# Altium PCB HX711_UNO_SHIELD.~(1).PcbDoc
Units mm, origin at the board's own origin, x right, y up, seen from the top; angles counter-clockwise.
Board outline 53.34 x 40.64 mm, 2 copper layers (Top Layer, Bottom Layer); 5 components, 8 nets, 35 pads, 0 vias.
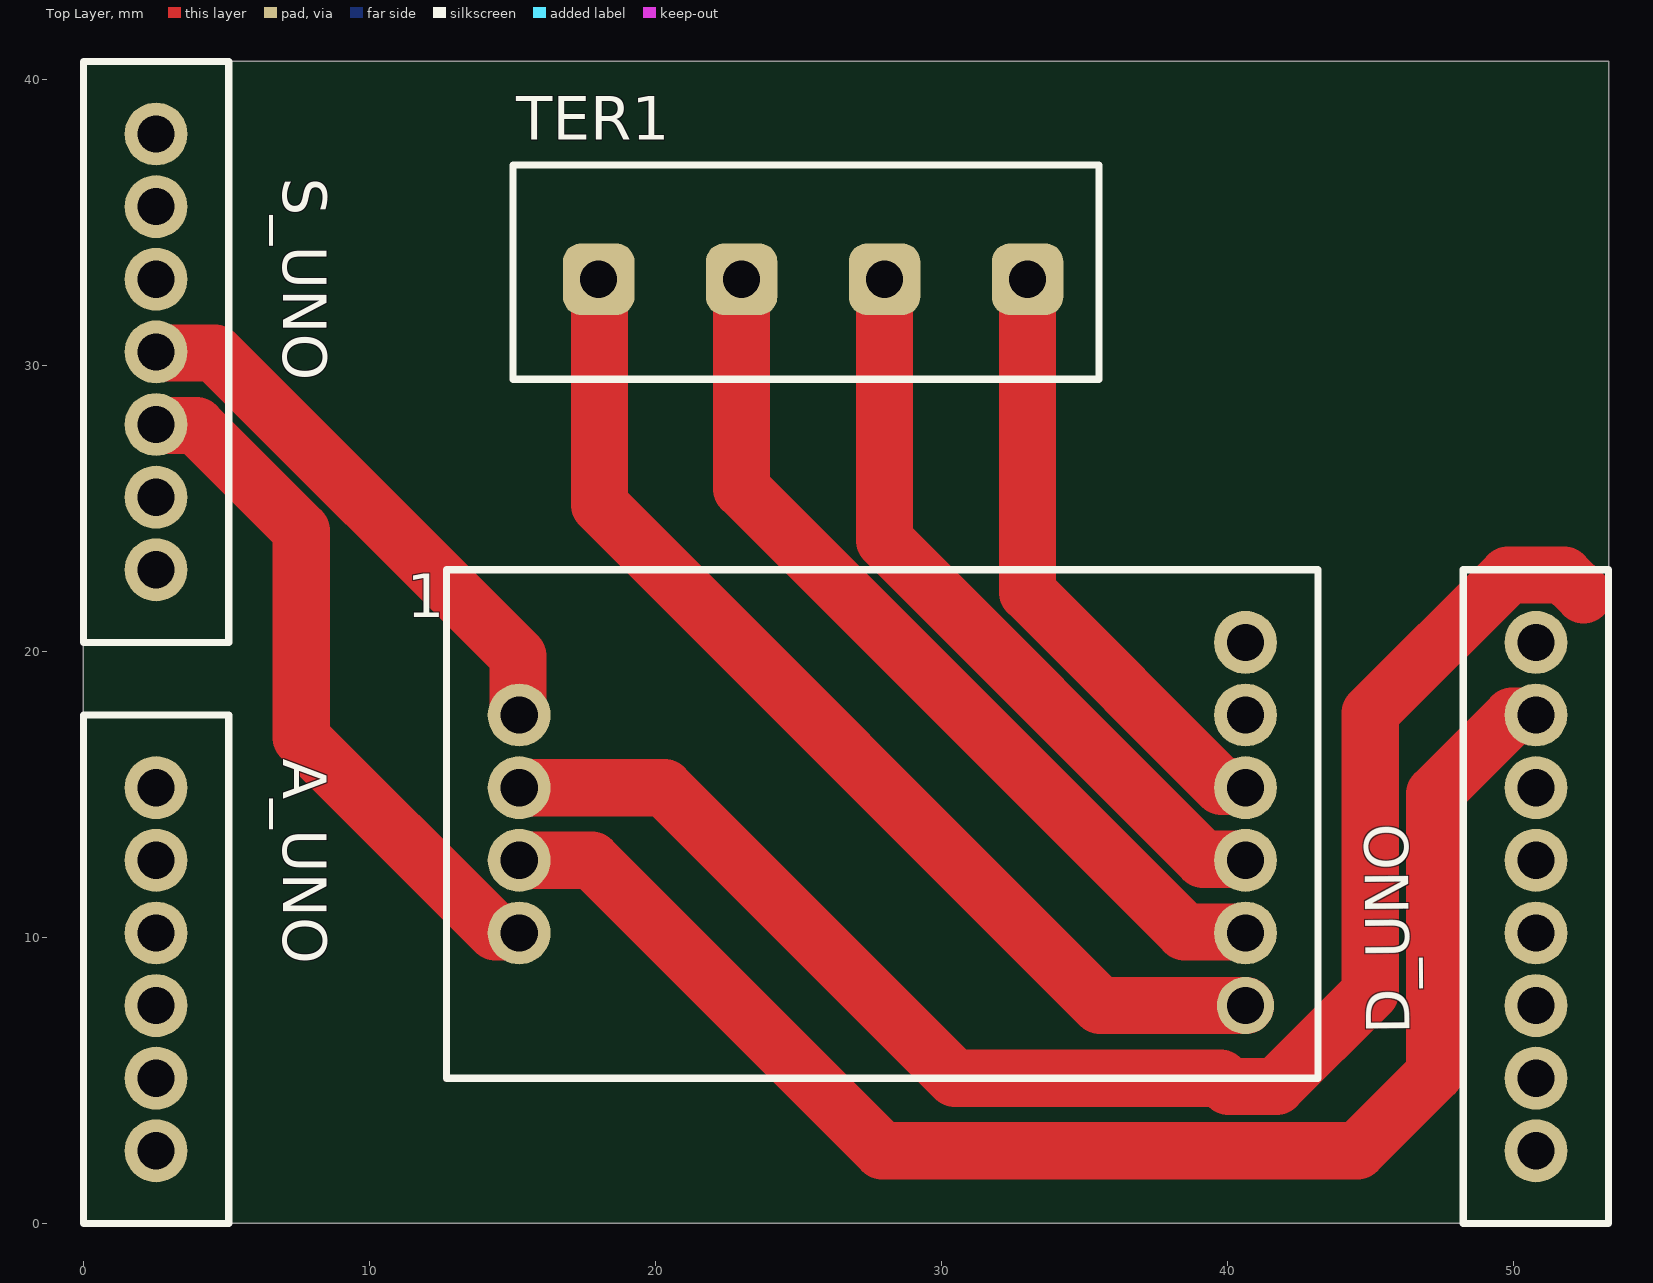
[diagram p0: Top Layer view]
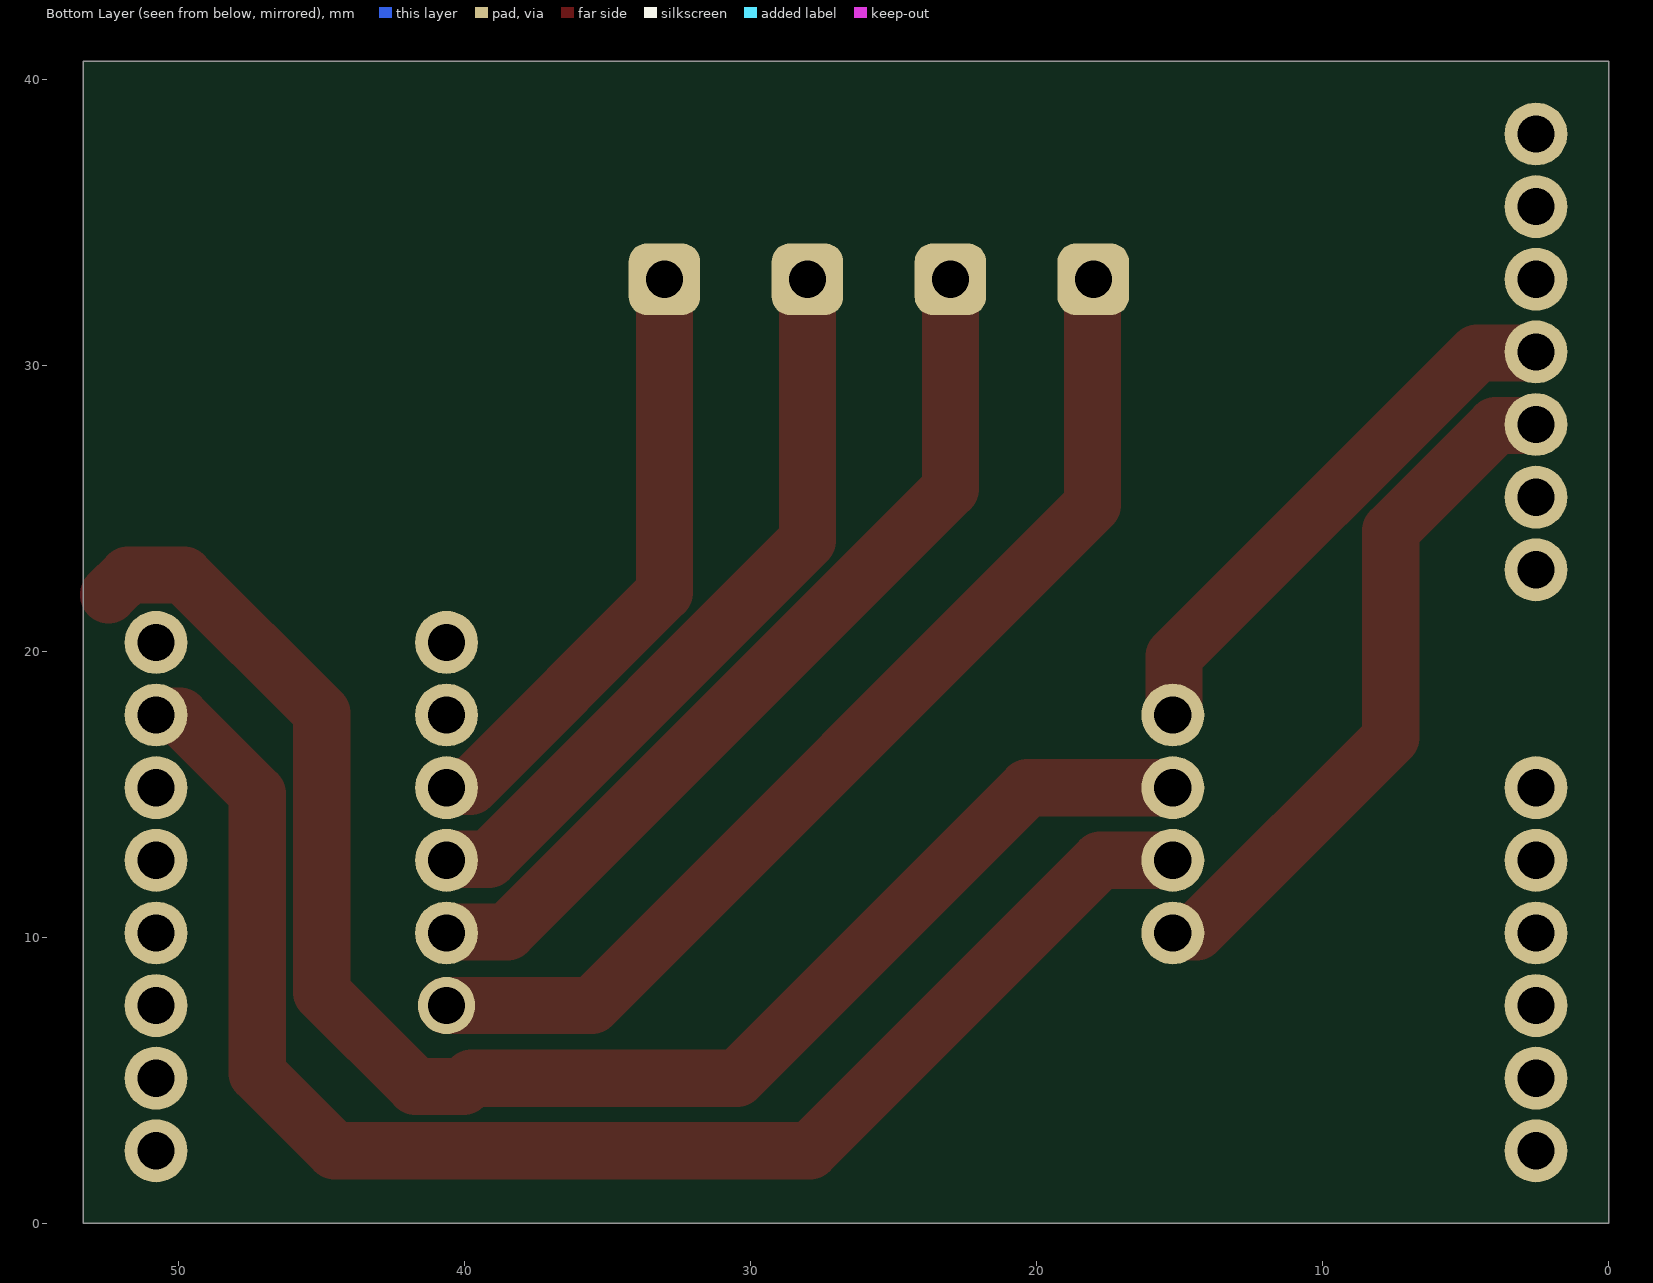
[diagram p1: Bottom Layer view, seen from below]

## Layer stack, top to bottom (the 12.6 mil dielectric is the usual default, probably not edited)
Top Solder: solder mask 0.0102, Solder Resist, Dk 3.5
Top Layer: signal copper 0.0356
Dielectric 1: dielectric 0.32, FR-4, Dk 4.8
Bottom Layer: signal copper 0.0356
Bottom Solder: solder mask 0.0102, Solder Resist, Dk 3.5

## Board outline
0,0 53.34,0 53.34,40.64 0,40.64

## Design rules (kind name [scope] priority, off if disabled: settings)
Clearance [All] p1: gap=0.254 ignorepadtopadclearanceinfootprint=FALSE except(0: Arc-Hole Track-Hole SMDPad-Hole THPad-Hole Via-Hole Fill-Hole Poly-Hole Region-Hole Text-Hole)
PolygonConnect [All] p1: connectstyle=Relief reliefconductorwidth=0.254 reliefentries=4 polygonreliefangle="90 Angle" airgapwidth=0.254
RoomDefinition hx711_uno_scheme [InComponentClass('hx711_uno_scheme')] p1: confinementstyle=ConfineIn formatcopy=TRUE lockcomponents=FALSE outline 0,0 53.34,0 53.34,40.64 0,40.64
RoutingVias [All] p1: holewidth=0.711 width=1.27 viastyle="Through Hole" minholewidth=0.711 minwidth=1.27 maxholewidth=0.711 maxwidth=1.27
SolderMaskExpansion [All] p1: expansion=0.102 istentingtop=FALSE
Width [All] p1: maxlimit=2.54 minlimit=0.254 preferedwidth=2
30 further rules are at their usual default settings.

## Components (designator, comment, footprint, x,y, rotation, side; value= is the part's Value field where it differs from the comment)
1 "HX711" HX711 40.64,7.62 r180 top
A_UNO "uno_analog" uno_analog 2.54,15.24 r0 top
D_UNO "uno_digital" uno_digital 50.8,2.54 r0 top
S_UNO "uno_source" uno_source 2.54,22.86 r0 top
TER1 "KF301_4" KF304_4 33.02,33.02 r270 top

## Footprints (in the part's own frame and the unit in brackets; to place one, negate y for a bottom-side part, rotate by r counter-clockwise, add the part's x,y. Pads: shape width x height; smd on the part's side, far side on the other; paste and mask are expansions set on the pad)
HX711 [mm]
  round 2 hole 1.3 paste+0 mask+0.102: 1(0,0)
  round 2.2 hole 1.3 paste+0 mask+0.102: 2(0,-2.54) 3(0,-5.08) 4(0,-7.62) 5(0,-10.16) 6(0,-12.7) 7(25.4,-2.54) 8(25.4,-5.08) 9(25.4,-7.62) 10(25.4,-10.16)
  silkscreen extent -2.54,-15.24 27.94,2.54
KF304_4 [mm]
  rrect50% 2.5x2.5 hole 1.3 paste+0 mask+0.102: 1(0,0) 2(0,-5) 3(0,-10) 4(0,-15)
  silkscreen extent -4,-18 3.5,2.5
uno_analog [mm]
  round 2.2 hole 1.3 paste+0 mask+0.102: 0(0,0) 1(0,-2.54) 2(0,-5.08) 3(0,-7.62) 4(0,-10.16) 5(0,-12.7)
  silkscreen extent -2.54,-15.24 2.54,2.54
uno_digital [mm]
  round 2.2 hole 1.3 paste+0 mask+0.102: 0(0,0) 1(0,2.54) 2(0,5.08) 3(0,7.62) 4(0,10.16) 5(0,12.7) 6(0,15.24) 7(0,17.78)
  silkscreen extent -2.54,-2.54 2.54,20.32
uno_source [mm]
  round 2.2 hole 1.3 paste+0 mask+0.102: 0(0,0) 1(0,2.54) 2(0,5.08) 3(0,7.62) 4(0,10.16) 5(0,12.7) 6(0,15.24)
  silkscreen extent -2.54,-2.54 2.54,17.78

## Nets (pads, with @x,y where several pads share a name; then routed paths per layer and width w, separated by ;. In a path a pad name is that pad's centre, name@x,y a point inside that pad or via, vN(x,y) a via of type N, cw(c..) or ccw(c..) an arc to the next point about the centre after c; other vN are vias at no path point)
Net1_1: 1.1 TER1.4 | length 37.7
  Top Layer w2: TER1.4 18.02,32.803 18.053,32.77 18.053,25.127 35.56,7.62 1.1
Net1_2: 1.2 TER1.3 | length 31.4
  Top Layer w2: TER1.3 23.02,25.696 38.517,10.198 40.602,10.198 1.2
Net1_3: 1.3 TER1.2 | length 26.4
  Top Layer w2: TER1.2 28.02,23.883 39.165,12.738 40.602,12.738 1.3
Net1_4: 1.4 TER1.1 | length 21.4
  Top Layer w2: TER1.1 33.02,22.071 39.813,15.278 40.602,15.278 1.4
Net1_7: 1.7 S_UNO.2 | length 24.3
  Top Layer w2: S_UNO.2 2.578,27.902 3.947,27.902 7.62,24.228 7.62,16.991 14.413,10.198 15.202,10.198 1.7
Net1_8: 1.8 D_UNO.6 | length 51.8
  Top Layer w2: 1.8 17.78,12.7 27.94,2.54 44.548,2.54 47.261,5.252 47.261,15.03 49.973,17.742 50.762,17.742 D_UNO.6
Net1_9: 1.9 | length 55
  Top Layer w2: 1.9 20.32,15.24 30.48,5.08 39.768,5.08 40.054,4.794 41.722,4.794 45.007,8.078 45.007,17.856 49.825,22.674 51.775,22.674 52.465,21.985
Net1_10: 1.10 S_UNO.3 | length 19.1
  Top Layer w2: S_UNO.3 2.578,30.442 4.594,30.442 15.202,19.834 15.202,17.818 1.10
pads on no net: 1.5 1.6 A_UNO.0 A_UNO.1 A_UNO.2 A_UNO.3 A_UNO.4 A_UNO.5 D_UNO.0 D_UNO.1 D_UNO.2 D_UNO.3 D_UNO.4 D_UNO.5 D_UNO.7 S_UNO.0 S_UNO.1 S_UNO.4 S_UNO.5 S_UNO.6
